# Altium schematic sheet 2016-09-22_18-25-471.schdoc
size 231 x 111 mm; SheetNumber: 1; SheetTotal: 1
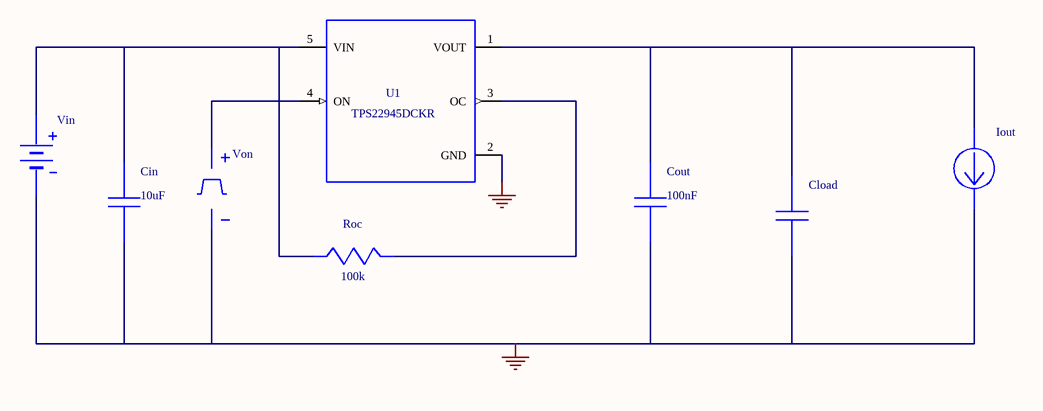
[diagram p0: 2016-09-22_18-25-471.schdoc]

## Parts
Cin  value 10uF  (hidden comment: CL10A106MQ8NNNC)
Cload  GRM21BR71E104KA01L  (value not drawn)
Cout  value 100nF  (hidden comment: GRM155R60J104KA01D)
Iout  WB_CURRENT_LOAD  (value not drawn)
Roc  value 100k  (hidden comment: CRCW0402100KFKED)
U1  TPS22945DCKR
Vin  WB_BATTERY  (value not drawn)
Von  WB_PRIM_PWL_VOLTAGE_SOURCE  (value not drawn)

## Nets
0: Cin.2 Cload.2 Cout.2 Iout.2(-) U1.2(GND) Vin.2(-) Von.2(-)
NetCin_1: Cin.1 Roc.2 U1.5(VIN) Vin.1(+)
NetCload_1: Cload.1 Cout.1 Iout.1(+) U1.1(VOUT)
NetRoc_1: Roc.1 U1.3(OC)
NetU1_4: U1.4(ON) Von.1(+)

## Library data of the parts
Cin = CL10A106MQ8NNNC: Manufacturer Name: Samsung Electro-Mechanics
Cload = GRM21BR71E104KA01L: WB_PRIMITIVE_CAP; Manufacturer Name: WB_PRIMITIVE_CAPACITOR
Cout = GRM155R60J104KA01D: GRM155R60J104KA0; Manufacturer Name: MuRata
Roc = CRCW0402100KFKED: Manufacturer Name: Vishay-Dale
U1 = TPS22945DCKR: Manufacturer Name: Texas Instruments
Von = WB_PRIM_PWL_VOLTAGE_SOURCE: WB_PRIM_PWL_VOLT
